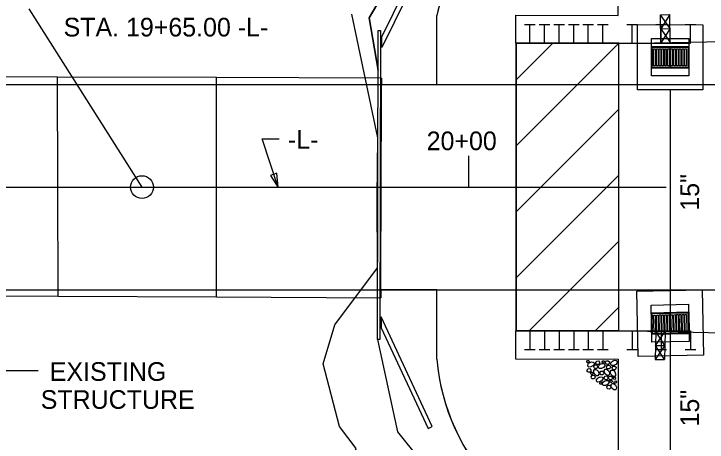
# Model space of a CAD drawing. Extents: x 471 to 2034, y -623 to 126.
# Drawn here: x 1574 to 1648.3, y -312.7 to -266.8 of the extents above; entities that cross this region are included whole.
import ezdxf

# ---------------------------------------------------------------- set-up
doc = ezdxf.new("R2010")
doc.units = 0
for name, color, linetype in [('Arrowhead Terminators CELL', 7, 'Continuous'), ('Default', 7, 'Continuous'), ('Dimension Lines', 7, 'Continuous'), ('Exist Hydro Stream or Body of Water', 7, 'Continuous'), ('Exist Structure Major Bridge WW', 7, 'Continuous'), ('Exist Structure Major Deck Tunnel Box Culvert', 7, 'Continuous'), ('Mis Object Lines', 7, 'Continuous'), ('Miscellaneous Lines CELL', 7, 'Continuous'), ('Prop EOT', 7, 'Continuous'), ('Prop Horizontal Alignment', 7, 'Continuous'), ('Prop Horizontal Alignment Tick Large', 7, 'Continuous'), ('Sup Concrete Girder Lines', 7, 'Continuous'), ('Text', 7, 'Continuous')]:
    doc.layers.add(name, color=color, linetype=linetype)

msp = doc.modelspace()

# ---------------------------------------------------------------- linework, layer by layer
at = {"layer": 'Arrowhead Terminators CELL'}
msp.add_lwpolyline([(1602.303, -285.453), (1602.19, -283.911), (1601.477, -284.145)], close=True, dxfattribs=at)
at = {"layer": 'Default'}
for p, q in [((1612.048, -267.252), (1617.565, -258.082)), ((1613.029, -272.865), (1612.048, -267.252)), ((1643.268, -266.935), (1644.268, -266.915)), ((1643.328, -269.934), (1643.268, -266.935)), ((1644.298, -268.414), (1643.268, -266.935)), ((1644.268, -266.915), (1643.298, -268.434)), ((1644.328, -269.914), (1644.268, -266.915)), ((1628.718, -267.989), (1629.864, -267.989)), ((1629.291, -269.989), (1629.291, -267.989)), ((1630.281, -267.989), (1631.426, -267.989)), ((1630.853, -269.989), (1630.853, -267.989)), ((1631.843, -267.989), (1632.988, -267.989)), ((1632.416, -269.989), (1632.416, -267.989)), ((1633.405, -267.989), (1634.551, -267.989)), ((1633.978, -269.989), (1633.978, -267.989)), ((1634.968, -267.989), (1636.113, -267.989)), ((1635.541, -269.989), (1635.541, -267.989)), ((1636.53, -267.989), (1637.676, -267.989)), ((1637.103, -269.989), (1637.103, -267.989)), ((1639.655, -267.989), (1640.801, -267.989)), ((1640.228, -269.989), (1640.228, -267.989)), ((1642.78, -267.989), (1643.926, -267.989)), ((1643.353, -269.989), (1643.353, -267.989)), ((1645.905, -267.989), (1647.051, -267.989)), ((1646.478, -269.989), (1646.478, -267.989)), ((1643.298, -268.434), (1644.298, -268.414)), ((1643.298, -268.434), (1644.328, -269.914)), ((1644.298, -268.414), (1643.328, -269.934)), ((1644.328, -269.914), (1644.298, -268.414)), ((1640.786, -269.985), (1687.528, -269.05)), ((1627.728, -269.989), (1646.478, -269.989)), ((1627.828, -269.989), (1627.828, -300.822)), ((1627.828, -300.822), (1627.828, -269.989)), ((1627.828, -269.989), (1638.828, -269.989)), ((1643.328, -269.934), (1644.328, -269.914)), ((1644.3, -270.323), (1644.3, -270.323)), ((1642.3, -271.489), (1642.3, -271.489)), ((1644.3, -271.49), (1644.3, -271.49)), ((1646.3, -271.491), (1646.3, -271.491)), ((1644.299, -272.657), (1644.299, -272.657)), ((1644.299, -298.83), (1644.299, -298.83)), ((1642.325, -300.039), (1642.325, -300.039)), ((1644.324, -299.996), (1644.324, -299.996)), ((1646.324, -299.953), (1646.324, -299.953)), ((1627.728, -300.822), (1646.478, -300.822)), ((1627.828, -300.822), (1638.828, -300.822)), ((1629.291, -300.822), (1629.291, -302.822)), ((1630.853, -300.822), (1630.853, -302.822)), ((1632.416, -300.822), (1632.416, -302.822)), ((1633.978, -300.822), (1633.978, -302.822)), ((1635.541, -300.822), (1635.541, -302.822)), ((1637.103, -300.822), (1637.103, -302.822)), ((1640.228, -300.822), (1640.228, -302.822)), ((1640.228, -300.822), (1686.97, -301.757)), ((1643.353, -300.822), (1643.353, -302.822)), ((1646.478, -300.822), (1646.478, -302.822)), ((1642.77, -300.873), (1642.71, -303.872)), ((1642.74, -302.373), (1643.77, -300.893)), ((1642.77, -300.873), (1643.77, -300.893)), ((1643.74, -302.393), (1642.77, -300.873)), ((1643.77, -300.893), (1643.71, -303.892)), ((1643.77, -300.893), (1643.74, -302.393)), ((1644.349, -301.163), (1644.349, -301.163)), ((1612.946, -301.732), (1615.117, -311.644)), ((1628.718, -302.822), (1629.864, -302.822)), ((1630.281, -302.822), (1631.426, -302.822)), ((1631.843, -302.822), (1632.988, -302.822)), ((1633.405, -302.822), (1634.551, -302.822)), ((1634.968, -302.822), (1636.113, -302.822)), ((1636.53, -302.822), (1637.676, -302.822)), ((1639.655, -302.822), (1640.801, -302.822)), ((1643.74, -302.393), (1642.71, -303.872)), ((1642.74, -302.373), (1643.74, -302.393)), ((1643.71, -303.892), (1642.74, -302.373)), ((1642.78, -302.822), (1643.926, -302.822)), ((1645.905, -302.822), (1647.051, -302.822)), ((1642.71, -303.872), (1643.71, -303.892)), ((1615.117, -311.644), (1622.006, -320.213))]:
    msp.add_line(p, q, dxfattribs=at)
for points in [[(1647.798, -274.991), (1640.798, -274.989), (1640.801, -267.989), (1647.801, -267.991)], [(1646.299, -273.491), (1642.299, -273.489), (1642.3, -269.489), (1646.3, -269.491)], [(1640.75, -296.572), (1647.748, -296.422), (1647.899, -303.42), (1640.9, -303.571)], [(1642.282, -298.04), (1646.281, -297.954), (1646.367, -301.953), (1642.368, -302.039)]]:
    msp.add_lwpolyline(points, close=True, dxfattribs=at)
for points in [[(1646.299, -272.657), (1642.299, -272.656), (1642.3, -270.323), (1646.3, -270.324), (1646.299, -272.657)], [(1646.237, -272.595), (1642.362, -272.593), (1642.363, -270.385), (1646.238, -270.387), (1646.237, -272.595)], [(1644.289, -272.584), (1642.372, -272.583), (1642.373, -270.396), (1644.29, -270.396), (1644.289, -272.584)], [(1642.716, -272.401), (1642.539, -272.401), (1642.54, -270.578), (1642.717, -270.578), (1642.716, -272.401)], [(1643.013, -272.401), (1642.836, -272.401), (1642.837, -270.578), (1643.014, -270.578), (1643.013, -272.401)], [(1643.31, -272.401), (1643.133, -272.401), (1643.134, -270.578), (1643.311, -270.578), (1643.31, -272.401)], [(1643.607, -272.401), (1643.43, -272.401), (1643.43, -270.578), (1643.607, -270.578), (1643.607, -272.401)], [(1643.904, -272.401), (1643.727, -272.401), (1643.727, -270.578), (1643.904, -270.578), (1643.904, -272.401)], [(1644.2, -272.401), (1644.023, -272.401), (1644.024, -270.578), (1644.201, -270.579), (1644.2, -272.401)], [(1646.226, -272.584), (1644.31, -272.584), (1644.311, -270.396), (1646.227, -270.397), (1646.226, -272.584)], [(1644.575, -272.402), (1644.398, -272.402), (1644.399, -270.579), (1644.576, -270.579), (1644.575, -272.402)], [(1644.872, -272.402), (1644.695, -272.402), (1644.696, -270.579), (1644.873, -270.579), (1644.872, -272.402)], [(1645.169, -272.402), (1644.992, -272.402), (1644.993, -270.579), (1645.17, -270.579), (1645.169, -272.402)], [(1645.466, -272.402), (1645.289, -272.402), (1645.29, -270.579), (1645.467, -270.579), (1645.466, -272.402)], [(1645.763, -272.402), (1645.586, -272.402), (1645.586, -270.579), (1645.764, -270.579), (1645.763, -272.402)], [(1646.06, -272.402), (1645.883, -272.402), (1645.883, -270.579), (1646.06, -270.579), (1646.06, -272.402)], [(1642.3, -298.873), (1646.299, -298.787), (1646.349, -301.12), (1642.35, -301.206), (1642.3, -298.873)], [(1642.364, -298.934), (1646.238, -298.851), (1646.285, -301.059), (1642.411, -301.142), (1642.364, -298.934)], [(1642.374, -298.944), (1644.29, -298.903), (1644.337, -301.09), (1642.421, -301.131), (1642.374, -298.944)], [(1642.545, -299.123), (1642.722, -299.119), (1642.761, -300.942), (1642.584, -300.945), (1642.545, -299.123)], [(1642.842, -299.116), (1643.019, -299.113), (1643.058, -300.935), (1642.881, -300.939), (1642.842, -299.116)], [(1643.138, -299.11), (1643.315, -299.106), (1643.355, -300.929), (1643.178, -300.933), (1643.138, -299.11)], [(1643.435, -299.104), (1643.612, -299.1), (1643.651, -300.922), (1643.474, -300.926), (1643.435, -299.104)], [(1643.732, -299.097), (1643.909, -299.094), (1643.948, -300.916), (1643.771, -300.92), (1643.732, -299.097)], [(1644.029, -299.091), (1644.206, -299.087), (1644.245, -300.91), (1644.068, -300.914), (1644.029, -299.091)], [(1644.311, -298.903), (1646.227, -298.862), (1646.274, -301.049), (1644.358, -301.09), (1644.311, -298.903)], [(1644.404, -299.083), (1644.581, -299.079), (1644.62, -300.902), (1644.443, -300.905), (1644.404, -299.083)], [(1644.7, -299.077), (1644.877, -299.073), (1644.917, -300.895), (1644.739, -300.899), (1644.7, -299.077)], [(1644.997, -299.07), (1645.174, -299.066), (1645.213, -300.889), (1645.036, -300.893), (1644.997, -299.07)], [(1645.294, -299.064), (1645.471, -299.06), (1645.51, -300.883), (1645.333, -300.886), (1645.294, -299.064)], [(1645.591, -299.058), (1645.768, -299.054), (1645.807, -300.876), (1645.63, -300.88), (1645.591, -299.058)], [(1645.888, -299.051), (1646.065, -299.047), (1646.104, -300.87), (1645.927, -300.874), (1645.888, -299.051)]]:
    msp.add_lwpolyline(points, dxfattribs=at)
at = {"layer": 'Dimension Lines'}
for p, q in [((1617.565, -258.082), (1612.048, -267.252)), ((1587.728, -285.405), (1575.643, -266.299)), ((1612.048, -267.252), (1613.029, -272.865)), ((1613.374, -274.405), (1619.32, -274.405)), ((1602.303, -285.453), (1600.584, -280.234)), ((1600.584, -280.234), (1602.421, -280.234)), ((1619.32, -296.405), (1613.311, -296.405)), ((1619.32, -303.846), (1619.32, -296.405)), ((1612.946, -301.732), (1615.117, -311.644)), ((1619.32, -303.854), (1619.32, -303.846)), ((1570.822, -305.058), (1576.593, -305.058)), ((1615.117, -311.644), (1622.006, -320.213))]:
    msp.add_line(p, q, dxfattribs=at)
for points in [[(1619.32, -274.405), (1619.32, -267.02), (1619.32, -267.013)], [(1613.029, -272.865), (1613.041, -268.611), (1613.291, -268.612), (1613.276, -273.709)], [(1613.276, -273.709), (1613.376, -273.71), (1613.374, -274.405)], [(1613.311, -296.405), (1613.309, -297.262), (1613.209, -297.261)], [(1613.209, -297.261), (1613.196, -301.733), (1612.946, -301.732)]]:
    msp.add_lwpolyline(points, dxfattribs=at)
msp.add_circle((1587.728, -285.405), 1.22, dxfattribs=at)
for centre, radius, start, end in [((1638.712, -270.982), 19.795, 119.31339, 168.43173), ((1641.983, -301.9), 22.747, 184.92778, 261.57569)]:
    msp.add_arc(centre, radius, start, end, dxfattribs=at)
at = {"layer": 'Exist Hydro Stream or Body of Water'}
for points in [[(1608.386, -300.151), (1612.944, -294.059), (1612.936, -286.496), (1612.991, -280.117), (1610.21, -266.858)], [(1604.706, -331.475), (1608.611, -318.808), (1610.676, -313.405), (1608.872, -311.072), (1607.133, -304.333), (1608.386, -300.151)]]:
    msp.add_lwpolyline(points, dxfattribs=at)
at = {"layer": 'Exist Structure Major Bridge WW'}
for points in [[(1613.421, -270.429), (1613.425, -269.291), (1618.44, -259.106), (1618.888, -259.327), (1613.421, -270.429)], [(1613.041, -268.611), (1613.291, -268.612), (1613.196, -301.733), (1612.946, -301.732), (1613.041, -268.611)], [(1613.338, -299.319), (1613.335, -300.494), (1618.37, -311.282), (1618.823, -311.07), (1613.338, -299.319)]]:
    msp.add_lwpolyline(points, dxfattribs=at)
at = {"layer": 'Exist Structure Major Deck Tunnel Box Culvert'}
for points in [[(1560.735, -292.199), (1560.745, -295.315), (1560.75, -297.001), (1578.739, -297.09), (1595.715, -297.175), (1613.309, -297.262), (1613.315, -294.996), (1613.343, -285.317), (1613.37, -275.815), (1613.376, -273.71), (1595.699, -273.66), (1578.686, -273.613), (1560.673, -273.562)], [(1578.739, -297.09), (1578.712, -285.245), (1578.686, -273.613)], [(1595.715, -297.175), (1595.707, -285.21), (1595.699, -273.66)]]:
    msp.add_lwpolyline(points, dxfattribs=at)
at = {"layer": 'Mis Object Lines'}
for p, q in [((1627.828, -269.989), (1627.828, -300.822)), ((1638.828, -269.989), (1627.828, -269.989)), ((1627.828, -280.989), (1638.828, -269.989)), ((1627.828, -273.918), (1631.757, -269.989)), ((1638.828, -300.822), (1638.828, -269.989)), ((1627.828, -288.06), (1638.828, -277.06)), ((1627.828, -295.131), (1638.828, -284.131)), ((1629.208, -300.822), (1638.828, -291.202)), ((1636.279, -300.822), (1638.828, -298.273)), ((1638.828, -300.822), (1627.828, -300.822))]:
    msp.add_line(p, q, dxfattribs=at)
at = {"layer": 'Miscellaneous Lines CELL'}
for points in [[(1635.385, -304.101), (1635.452, -304.005), (1635.56, -303.999), (1635.634, -304.076), (1635.624, -304.185), (1635.557, -304.24), (1635.451, -304.232), (1635.401, -304.184), (1635.385, -304.101)], [(1635.676, -304.223), (1635.885, -304.14), (1636.078, -304.157), (1636.169, -304.244), (1636.166, -304.4), (1636.027, -304.578), (1635.813, -304.685), (1635.61, -304.688), (1635.497, -304.608), (1635.486, -304.446), (1635.578, -304.302), (1635.684, -304.218)], [(1636.129, -304.624), (1636.241, -304.465), (1636.419, -304.455), (1636.544, -304.584), (1636.526, -304.765), (1636.415, -304.856), (1636.239, -304.844), (1636.156, -304.763), (1636.129, -304.625)], [(1636.339, -304.203), (1636.451, -304.043), (1636.63, -304.033), (1636.755, -304.162), (1636.737, -304.343), (1636.626, -304.435), (1636.45, -304.422), (1636.366, -304.341), (1636.339, -304.203)], [(1636.814, -304.393), (1637.024, -304.31), (1637.216, -304.326), (1637.308, -304.413), (1637.305, -304.569), (1637.166, -304.747), (1636.951, -304.854), (1636.749, -304.858), (1636.635, -304.777), (1636.625, -304.616), (1636.717, -304.472), (1636.823, -304.387)], [(1637.019, -304.137), (1637.086, -304.042), (1637.194, -304.036), (1637.268, -304.113), (1637.258, -304.221), (1637.191, -304.276), (1637.085, -304.269), (1637.035, -304.22), (1637.019, -304.137)], [(1637.386, -304.179), (1637.498, -304.019), (1637.677, -304.009), (1637.802, -304.138), (1637.784, -304.319), (1637.673, -304.411), (1637.497, -304.398), (1637.413, -304.317), (1637.387, -304.179)], [(1637.492, -304.656), (1637.604, -304.496), (1637.783, -304.486), (1637.907, -304.615), (1637.889, -304.796), (1637.779, -304.888), (1637.602, -304.875), (1637.519, -304.794), (1637.492, -304.656)], [(1638.138, -304.051), (1638.348, -303.968), (1638.54, -303.985), (1638.632, -304.072), (1638.629, -304.228), (1638.49, -304.406), (1638.276, -304.513), (1638.073, -304.516), (1637.959, -304.435), (1637.949, -304.274), (1638.041, -304.13), (1638.147, -304.046)], [(1635.41, -305.024), (1635.522, -304.865), (1635.701, -304.855), (1635.825, -304.984), (1635.807, -305.164), (1635.697, -305.256), (1635.52, -305.244), (1635.437, -305.163), (1635.41, -305.024)], [(1635.795, -305.351), (1635.862, -305.255), (1635.97, -305.249), (1636.044, -305.327), (1636.033, -305.435), (1635.967, -305.49), (1635.861, -305.482), (1635.811, -305.434), (1635.795, -305.351)], [(1636.586, -305.137), (1636.669, -305.347), (1636.653, -305.539), (1636.566, -305.631), (1636.409, -305.628), (1636.232, -305.489), (1636.125, -305.274), (1636.121, -305.072), (1636.202, -304.958), (1636.363, -304.947), (1636.507, -305.04), (1636.592, -305.145)], [(1636.788, -305.296), (1636.9, -305.136), (1637.078, -305.126), (1637.203, -305.255), (1637.185, -305.436), (1637.074, -305.527), (1636.898, -305.515), (1636.815, -305.434), (1636.788, -305.296)], [(1637.725, -305.11), (1637.808, -305.319), (1637.791, -305.512), (1637.704, -305.604), (1637.548, -305.601), (1637.371, -305.462), (1637.263, -305.247), (1637.26, -305.045), (1637.341, -304.931), (1637.502, -304.92), (1637.646, -305.012), (1637.73, -305.118)], [(1638.389, -305.211), (1638.472, -305.421), (1638.456, -305.614), (1638.369, -305.705), (1638.213, -305.702), (1638.035, -305.563), (1637.928, -305.349), (1637.924, -305.146), (1638.005, -305.033), (1638.166, -305.022), (1638.31, -305.114), (1638.395, -305.22)], [(1638.104, -304.753), (1638.216, -304.594), (1638.395, -304.584), (1638.52, -304.713), (1638.502, -304.893), (1638.391, -304.985), (1638.215, -304.973), (1638.131, -304.892), (1638.105, -304.753)], [(1635.852, -305.736), (1635.964, -305.577), (1636.143, -305.567), (1636.267, -305.695), (1636.249, -305.876), (1636.139, -305.968), (1635.962, -305.955), (1635.879, -305.875), (1635.852, -305.736)], [(1636.611, -305.83), (1636.821, -305.747), (1637.013, -305.763), (1637.105, -305.85), (1637.102, -306.006), (1636.963, -306.184), (1636.748, -306.291), (1636.546, -306.295), (1636.432, -306.214), (1636.421, -306.053), (1636.514, -305.909), (1636.619, -305.824)], [(1637.236, -305.815), (1637.348, -305.656), (1637.527, -305.646), (1637.651, -305.774), (1637.633, -305.955), (1637.523, -306.047), (1637.346, -306.034), (1637.263, -305.954), (1637.236, -305.815)], [(1637.697, -305.822), (1637.809, -305.662), (1637.988, -305.652), (1638.112, -305.781), (1638.094, -305.962), (1637.984, -306.054), (1637.807, -306.041), (1637.724, -305.96), (1637.697, -305.822)], [(1638.207, -305.871), (1638.274, -305.775), (1638.381, -305.769), (1638.456, -305.847), (1638.445, -305.955), (1638.379, -306.01), (1638.273, -306.003), (1638.223, -305.954), (1638.207, -305.871)], [(1636.762, -306.391), (1636.829, -306.296), (1636.936, -306.29), (1637.011, -306.367), (1637, -306.475), (1636.934, -306.53), (1636.828, -306.523), (1636.778, -306.474), (1636.762, -306.391)], [(1637.261, -306.204), (1637.471, -306.121), (1637.663, -306.138), (1637.755, -306.225), (1637.752, -306.381), (1637.613, -306.558), (1637.398, -306.666), (1637.196, -306.669), (1637.082, -306.588), (1637.072, -306.427), (1637.164, -306.283), (1637.27, -306.199)], [(1637.536, -306.812), (1637.648, -306.653), (1637.827, -306.643), (1637.951, -306.772), (1637.933, -306.952), (1637.823, -307.044), (1637.646, -307.032), (1637.563, -306.951), (1637.536, -306.813)], [(1637.86, -306.207), (1637.927, -306.112), (1638.034, -306.106), (1638.109, -306.183), (1638.098, -306.291), (1638.032, -306.347), (1637.926, -306.339), (1637.876, -306.291), (1637.86, -306.207)], [(1638.471, -306.642), (1638.554, -306.851), (1638.537, -307.044), (1638.45, -307.135), (1638.294, -307.132), (1638.116, -306.994), (1638.009, -306.779), (1638.005, -306.577), (1638.086, -306.463), (1638.247, -306.452), (1638.392, -306.544), (1638.476, -306.65)], [(1638.301, -306.286), (1638.368, -306.191), (1638.476, -306.184), (1638.55, -306.262), (1638.54, -306.37), (1638.473, -306.425), (1638.367, -306.418), (1638.317, -306.369), (1638.301, -306.286)]]:
    msp.add_lwpolyline(points, dxfattribs=at)
at = {"layer": 'Prop EOT'}
for p, q in [((1473.051, -274.405), (1714.024, -274.405)), ((1473.051, -296.405), (1714.024, -296.405))]:
    msp.add_line(p, q, dxfattribs=at)
at = {"layer": 'Prop Horizontal Alignment'}
msp.add_line((1473.051, -285.405), (1643.881, -285.405), dxfattribs=at)
at = {"layer": 'Prop Horizontal Alignment Tick Large'}
msp.add_line((1622.728, -285.405), (1622.728, -282.041), dxfattribs=at)
at = {"layer": 'Sup Concrete Girder Lines'}
for p, q in [((1638.728, -267.02), (1638.728, -251.195)), ((1627.728, -266.989), (1627.728, -269.989)), ((1627.728, -266.989), (1638.728, -267.02)), ((1644.3, -270.323), (1644.3, -270.323)), ((1642.3, -271.489), (1642.3, -271.489)), ((1644.3, -271.49), (1644.3, -271.49)), ((1646.3, -271.491), (1646.3, -271.491)), ((1644.299, -272.657), (1644.299, -272.657)), ((1644.302, -274.99), (1644.297, -313.744)), ((1644.299, -298.83), (1644.299, -298.83)), ((1642.325, -300.039), (1642.325, -300.039)), ((1644.324, -299.996), (1644.324, -299.996)), ((1646.324, -299.953), (1646.324, -299.953)), ((1627.728, -300.822), (1627.728, -303.822)), ((1644.349, -301.163), (1644.349, -301.163)), ((1627.728, -303.822), (1638.728, -303.854)), ((1638.728, -303.854), (1638.728, -324.405))]:
    msp.add_line(p, q, dxfattribs=at)
for points in [[(1647.798, -274.991), (1640.798, -274.989), (1640.801, -267.989), (1647.801, -267.991)], [(1646.299, -273.491), (1642.299, -273.489), (1642.3, -269.489), (1646.3, -269.491)], [(1640.75, -296.572), (1647.748, -296.422), (1647.899, -303.42), (1640.9, -303.571)], [(1642.282, -298.04), (1646.281, -297.954), (1646.367, -301.953), (1642.368, -302.039)]]:
    msp.add_lwpolyline(points, close=True, dxfattribs=at)
for points in [[(1646.299, -272.657), (1642.299, -272.656), (1642.3, -270.323), (1646.3, -270.324), (1646.299, -272.657)], [(1646.237, -272.595), (1642.362, -272.593), (1642.363, -270.385), (1646.238, -270.387), (1646.237, -272.595)], [(1644.289, -272.584), (1642.372, -272.583), (1642.373, -270.396), (1644.29, -270.396), (1644.289, -272.584)], [(1642.716, -272.401), (1642.539, -272.401), (1642.54, -270.578), (1642.717, -270.578), (1642.716, -272.401)], [(1643.013, -272.401), (1642.836, -272.401), (1642.837, -270.578), (1643.014, -270.578), (1643.013, -272.401)], [(1643.31, -272.401), (1643.133, -272.401), (1643.134, -270.578), (1643.311, -270.578), (1643.31, -272.401)], [(1643.607, -272.401), (1643.43, -272.401), (1643.43, -270.578), (1643.607, -270.578), (1643.607, -272.401)], [(1643.904, -272.401), (1643.727, -272.401), (1643.727, -270.578), (1643.904, -270.578), (1643.904, -272.401)], [(1644.2, -272.401), (1644.023, -272.401), (1644.024, -270.578), (1644.201, -270.579), (1644.2, -272.401)], [(1646.226, -272.584), (1644.31, -272.584), (1644.311, -270.396), (1646.227, -270.397), (1646.226, -272.584)], [(1644.575, -272.402), (1644.398, -272.402), (1644.399, -270.579), (1644.576, -270.579), (1644.575, -272.402)], [(1644.872, -272.402), (1644.695, -272.402), (1644.696, -270.579), (1644.873, -270.579), (1644.872, -272.402)], [(1645.169, -272.402), (1644.992, -272.402), (1644.993, -270.579), (1645.17, -270.579), (1645.169, -272.402)], [(1645.466, -272.402), (1645.289, -272.402), (1645.29, -270.579), (1645.467, -270.579), (1645.466, -272.402)], [(1645.763, -272.402), (1645.586, -272.402), (1645.586, -270.579), (1645.764, -270.579), (1645.763, -272.402)], [(1646.06, -272.402), (1645.883, -272.402), (1645.883, -270.579), (1646.06, -270.579), (1646.06, -272.402)], [(1642.3, -298.873), (1646.299, -298.787), (1646.349, -301.12), (1642.35, -301.206), (1642.3, -298.873)], [(1642.364, -298.934), (1646.238, -298.851), (1646.285, -301.059), (1642.411, -301.142), (1642.364, -298.934)], [(1642.374, -298.944), (1644.29, -298.903), (1644.337, -301.09), (1642.421, -301.131), (1642.374, -298.944)], [(1642.545, -299.123), (1642.722, -299.119), (1642.761, -300.942), (1642.584, -300.945), (1642.545, -299.123)], [(1642.842, -299.116), (1643.019, -299.113), (1643.058, -300.935), (1642.881, -300.939), (1642.842, -299.116)], [(1643.138, -299.11), (1643.315, -299.106), (1643.355, -300.929), (1643.178, -300.933), (1643.138, -299.11)], [(1643.435, -299.104), (1643.612, -299.1), (1643.651, -300.922), (1643.474, -300.926), (1643.435, -299.104)], [(1643.732, -299.097), (1643.909, -299.094), (1643.948, -300.916), (1643.771, -300.92), (1643.732, -299.097)], [(1644.029, -299.091), (1644.206, -299.087), (1644.245, -300.91), (1644.068, -300.914), (1644.029, -299.091)], [(1644.311, -298.903), (1646.227, -298.862), (1646.274, -301.049), (1644.358, -301.09), (1644.311, -298.903)], [(1644.404, -299.083), (1644.581, -299.079), (1644.62, -300.902), (1644.443, -300.905), (1644.404, -299.083)], [(1644.7, -299.077), (1644.877, -299.073), (1644.917, -300.895), (1644.739, -300.899), (1644.7, -299.077)], [(1644.997, -299.07), (1645.174, -299.066), (1645.213, -300.889), (1645.036, -300.893), (1644.997, -299.07)], [(1645.294, -299.064), (1645.471, -299.06), (1645.51, -300.883), (1645.333, -300.886), (1645.294, -299.064)], [(1645.591, -299.058), (1645.768, -299.054), (1645.807, -300.876), (1645.63, -300.88), (1645.591, -299.058)], [(1645.888, -299.051), (1646.065, -299.047), (1646.104, -300.87), (1645.927, -300.874), (1645.888, -299.051)]]:
    msp.add_lwpolyline(points, dxfattribs=at)
for centre, radius, start, end in [((1638.712, -270.982), 19.795, 89.95342, 168.43173), ((1638.712, -270.99), 19.795, 160.55456, 168.43173), ((1641.983, -301.892), 22.747, 184.92778, 261.77484), ((1641.983, -301.9), 22.747, 184.92778, 261.77484)]:
    msp.add_arc(centre, radius, start, end, dxfattribs=at)

# ---------------------------------------------------------------- texts
at = {"layer": 'Text'}
for s, p in [('STA. 19+65.00 -L-', (1579.328, -269.256)), ('-L-', (1603.357, -281.294)), ('20+00', (1618.225, -281.445)), ('EXISTING', (1577.846, -306.17)), ('STRUCTURE', (1576.877, -309.17))]:
    msp.add_text(s, height=2, dxfattribs=at).set_placement(p)
for p in [(1647.418, -287.928), (1647.418, -311.061)]:
    msp.add_text('15"', height=2, rotation=90, dxfattribs=at).set_placement(p)

doc.saveas('drawing.dxf')
